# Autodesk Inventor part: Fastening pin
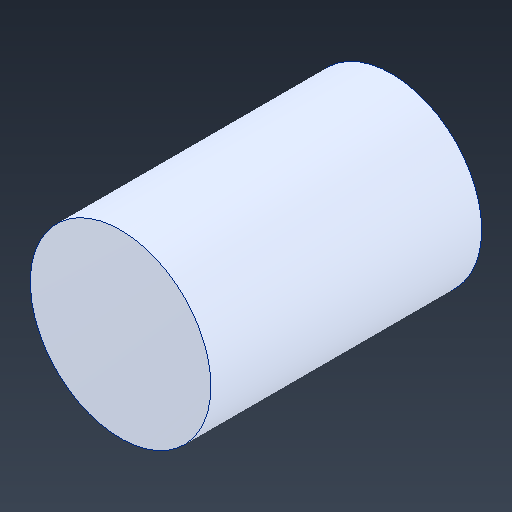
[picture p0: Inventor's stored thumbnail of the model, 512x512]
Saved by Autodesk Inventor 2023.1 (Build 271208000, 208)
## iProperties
Created: 2020-02
Part Number: Fastening pin
Material: SOLIDWORKS Materials|6061 Alloy
Document SubType Name: Modeling
Designer: ftrauzettel
Density: 2.7 g/cm^3
Appearance: 221,232,255
Sending System: SolidWorks 2016
Last Author: Pam
Last Saved: 2020-02-18
Author: ftrauzettel
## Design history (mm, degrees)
feature "Boss-Extrude1"
body "Solid1"
